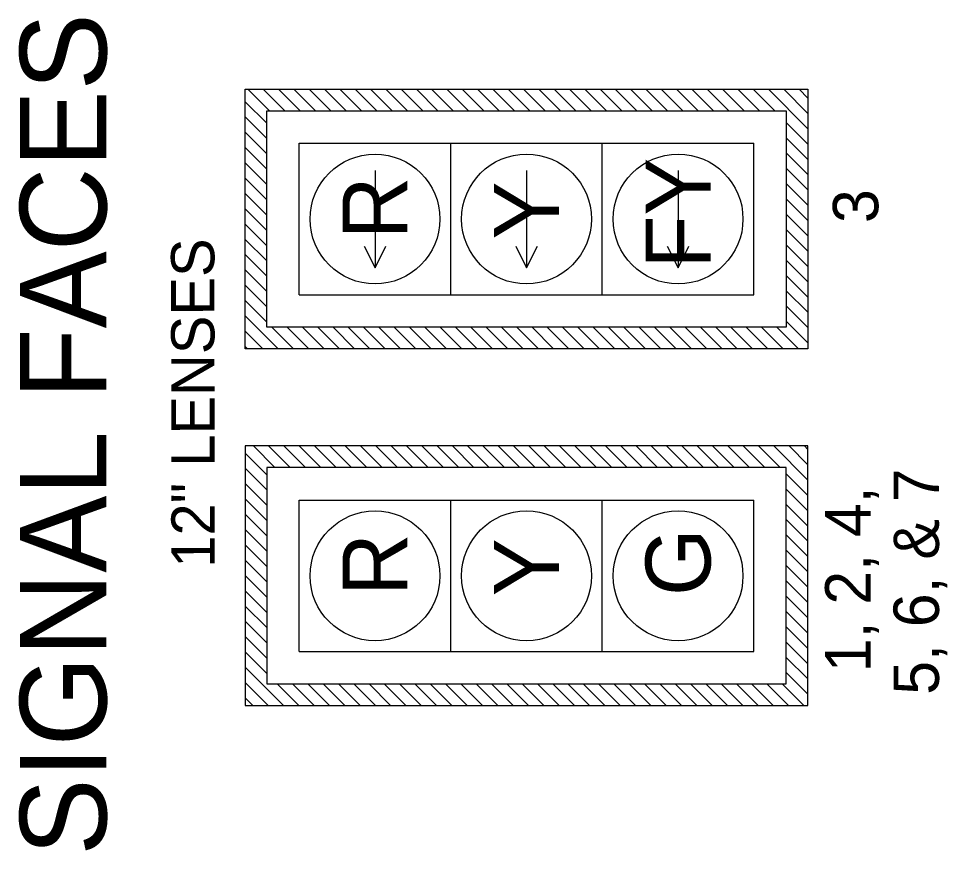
# Model space of a CAD drawing. Extents: x 610543 to 611161, y 419122 to 420064.
# Drawn here: x 610545.3 to 610631.1, y 419293.9 to 419370.8 of the extents above; entities that cross this region are included whole.
import ezdxf

# ---------------------------------------------------------------- set-up
doc = ezdxf.new("R2010")
doc.units = 0
for name, color, linetype in [('C-ANNO-TEXT', 7, 'Continuous'), ('Level 61', 7, 'Continuous'), ('T_Drafting', 7, 'Continuous')]:
    doc.layers.add(name, color=color, linetype=linetype)

msp = doc.modelspace()

# ---------------------------------------------------------------- linework, layer by layer
at = {"layer": 'T_Drafting'}
for p, q in [((610566.202, 419340.257), (610566.202, 419364.257)), ((610566.202, 419364.257), (610618.202, 419364.257)), ((610568.465, 419362.257), (610566.465, 419364.257)), ((610569.879, 419362.257), (610567.879, 419364.257)), ((610571.293, 419362.257), (610569.293, 419364.257)), ((610572.708, 419362.257), (610570.708, 419364.257)), ((610574.122, 419362.257), (610572.122, 419364.257)), ((610575.536, 419362.257), (610573.536, 419364.257)), ((610576.95, 419362.257), (610574.95, 419364.257)), ((610578.364, 419362.257), (610576.364, 419364.257)), ((610579.779, 419362.257), (610577.779, 419364.257)), ((610581.193, 419362.257), (610579.193, 419364.257)), ((610582.607, 419362.257), (610580.607, 419364.257)), ((610584.021, 419362.257), (610582.021, 419364.257)), ((610585.436, 419362.257), (610583.436, 419364.257)), ((610586.85, 419362.257), (610584.85, 419364.257)), ((610588.264, 419362.257), (610586.264, 419364.257)), ((610589.678, 419362.257), (610587.678, 419364.257)), ((610591.092, 419362.257), (610589.092, 419364.257)), ((610592.507, 419362.257), (610590.507, 419364.257)), ((610593.921, 419362.257), (610591.921, 419364.257)), ((610595.335, 419362.257), (610593.335, 419364.257)), ((610596.749, 419362.257), (610594.749, 419364.257)), ((610598.163, 419362.257), (610596.163, 419364.257)), ((610599.578, 419362.257), (610597.578, 419364.257)), ((610600.992, 419362.257), (610598.992, 419364.257)), ((610602.406, 419362.257), (610600.406, 419364.257)), ((610603.82, 419362.257), (610601.82, 419364.257)), ((610605.235, 419362.257), (610603.235, 419364.257)), ((610606.649, 419362.257), (610604.649, 419364.257)), ((610608.063, 419362.257), (610606.063, 419364.257)), ((610609.477, 419362.257), (610607.477, 419364.257)), ((610610.891, 419362.257), (610608.891, 419364.257)), ((610612.306, 419362.257), (610610.306, 419364.257)), ((610613.72, 419362.257), (610611.72, 419364.257)), ((610615.134, 419362.257), (610613.134, 419364.257)), ((610618.202, 419360.603), (610614.548, 419364.257)), ((610618.202, 419362.018), (610615.962, 419364.257)), ((610618.202, 419363.432), (610617.377, 419364.257)), ((610618.202, 419364.257), (610618.202, 419340.257)), ((610568.202, 419361.106), (610566.202, 419363.106)), ((610568.202, 419359.692), (610566.202, 419361.692)), ((610618.202, 419359.189), (610616.202, 419361.189)), ((610568.202, 419358.277), (610566.202, 419360.277)), ((610618.202, 419357.775), (610616.202, 419359.775)), ((610568.202, 419356.863), (610566.202, 419358.863)), ((610571.202, 419345.257), (610571.202, 419359.257)), ((610571.202, 419359.257), (610585.202, 419359.257)), ((610585.202, 419345.257), (610585.202, 419359.257)), ((610585.202, 419359.257), (610599.202, 419359.257)), ((610599.202, 419345.257), (610599.202, 419359.257)), ((610599.202, 419359.257), (610613.202, 419359.257)), ((610613.202, 419345.257), (610613.202, 419359.257)), ((610618.202, 419356.361), (610616.202, 419358.361)), ((610568.202, 419355.449), (610566.202, 419357.449)), ((610578.202, 419356.757), (610578.202, 419347.757)), ((610592.202, 419356.757), (610592.202, 419347.757)), ((610606.202, 419356.757), (610606.202, 419347.757)), ((610618.202, 419354.946), (610616.202, 419356.946)), ((610568.202, 419354.035), (610566.202, 419356.035)), ((610618.202, 419353.532), (610616.202, 419355.532)), ((610568.202, 419352.621), (610566.202, 419354.621)), ((610618.202, 419352.118), (610616.202, 419354.118)), ((610568.202, 419351.206), (610566.202, 419353.206)), ((610618.202, 419350.704), (610616.202, 419352.704)), ((610568.202, 419349.792), (610566.202, 419351.792)), ((610618.202, 419349.29), (610616.202, 419351.29)), ((610568.202, 419348.378), (610566.202, 419350.378)), ((610618.202, 419347.875), (610616.202, 419349.875)), ((610568.202, 419346.964), (610566.202, 419348.964)), ((610618.202, 419346.461), (610616.202, 419348.461)), ((610568.202, 419345.549), (610566.202, 419347.549)), ((610618.202, 419345.047), (610616.202, 419347.047)), ((610568.202, 419344.135), (610566.202, 419346.135)), ((610618.202, 419343.633), (610616.202, 419345.633)), ((610568.202, 419342.721), (610566.202, 419344.721)), ((610571.202, 419345.257), (610585.202, 419345.257)), ((610585.202, 419345.257), (610599.202, 419345.257)), ((610599.202, 419345.257), (610613.202, 419345.257)), ((610618.202, 419342.219), (610616.202, 419344.219)), ((610569.252, 419340.257), (610566.202, 419343.307)), ((610570.666, 419340.257), (610568.666, 419342.257)), ((610572.08, 419340.257), (610570.08, 419342.257)), ((610573.494, 419340.257), (610571.494, 419342.257)), ((610574.909, 419340.257), (610572.909, 419342.257)), ((610576.323, 419340.257), (610574.323, 419342.257)), ((610577.737, 419340.257), (610575.737, 419342.257)), ((610579.151, 419340.257), (610577.151, 419342.257)), ((610580.565, 419340.257), (610578.565, 419342.257)), ((610581.98, 419340.257), (610579.98, 419342.257)), ((610583.394, 419340.257), (610581.394, 419342.257)), ((610584.808, 419340.257), (610582.808, 419342.257)), ((610586.222, 419340.257), (610584.222, 419342.257)), ((610587.637, 419340.257), (610585.637, 419342.257)), ((610589.051, 419340.257), (610587.051, 419342.257)), ((610590.465, 419340.257), (610588.465, 419342.257)), ((610591.879, 419340.257), (610589.879, 419342.257)), ((610593.293, 419340.257), (610591.293, 419342.257)), ((610594.708, 419340.257), (610592.708, 419342.257)), ((610596.122, 419340.257), (610594.122, 419342.257)), ((610597.536, 419340.257), (610595.536, 419342.257)), ((610598.95, 419340.257), (610596.95, 419342.257)), ((610600.364, 419340.257), (610598.364, 419342.257)), ((610601.779, 419340.257), (610599.779, 419342.257)), ((610603.193, 419340.257), (610601.193, 419342.257)), ((610604.607, 419340.257), (610602.607, 419342.257)), ((610606.021, 419340.257), (610604.021, 419342.257)), ((610607.436, 419340.257), (610605.436, 419342.257)), ((610608.85, 419340.257), (610606.85, 419342.257)), ((610610.264, 419340.257), (610608.264, 419342.257)), ((610611.678, 419340.257), (610609.678, 419342.257)), ((610613.092, 419340.257), (610611.092, 419342.257)), ((610614.507, 419340.257), (610612.507, 419342.257)), ((610615.921, 419340.257), (610613.921, 419342.257)), ((610617.335, 419340.257), (610615.335, 419342.257)), ((610618.202, 419340.804), (610616.202, 419342.804)), ((610567.838, 419340.257), (610566.202, 419341.893)), ((610566.423, 419340.257), (610566.202, 419340.478)), ((610618.202, 419340.257), (610566.202, 419340.257)), ((610618.202, 419331.278), (610566.202, 419331.278)), ((610566.202, 419331.278), (610566.202, 419307.278)), ((610568.962, 419329.278), (610566.962, 419331.278)), ((610570.376, 419329.278), (610568.376, 419331.278)), ((610571.79, 419329.278), (610569.79, 419331.278)), ((610573.204, 419329.278), (610571.204, 419331.278)), ((610574.619, 419329.278), (610572.619, 419331.278)), ((610576.033, 419329.278), (610574.033, 419331.278)), ((610577.447, 419329.278), (610575.447, 419331.278)), ((610578.861, 419329.278), (610576.861, 419331.278)), ((610580.276, 419329.278), (610578.276, 419331.278)), ((610581.69, 419329.278), (610579.69, 419331.278)), ((610583.104, 419329.278), (610581.104, 419331.278)), ((610584.518, 419329.278), (610582.518, 419331.278)), ((610585.932, 419329.278), (610583.932, 419331.278)), ((610587.347, 419329.278), (610585.347, 419331.278)), ((610588.761, 419329.278), (610586.761, 419331.278)), ((610590.175, 419329.278), (610588.175, 419331.278)), ((610591.589, 419329.278), (610589.589, 419331.278)), ((610593.003, 419329.278), (610591.003, 419331.278)), ((610594.418, 419329.278), (610592.418, 419331.278)), ((610595.832, 419329.278), (610593.832, 419331.278)), ((610597.246, 419329.278), (610595.246, 419331.278)), ((610598.66, 419329.278), (610596.66, 419331.278)), ((610600.075, 419329.278), (610598.075, 419331.278)), ((610601.489, 419329.278), (610599.489, 419331.278)), ((610602.903, 419329.278), (610600.903, 419331.278)), ((610604.317, 419329.278), (610602.317, 419331.278)), ((610605.731, 419329.278), (610603.731, 419331.278)), ((610607.146, 419329.278), (610605.146, 419331.278)), ((610608.56, 419329.278), (610606.56, 419331.278)), ((610609.974, 419329.278), (610607.974, 419331.278)), ((610611.388, 419329.278), (610609.388, 419331.278)), ((610612.802, 419329.278), (610610.802, 419331.278)), ((610614.217, 419329.278), (610612.217, 419331.278)), ((610615.631, 419329.278), (610613.631, 419331.278)), ((610618.202, 419328.121), (610615.045, 419331.278)), ((610618.202, 419329.536), (610616.459, 419331.278)), ((610618.202, 419330.95), (610617.874, 419331.278)), ((610618.202, 419307.278), (610618.202, 419331.278)), ((610568.202, 419328.624), (610566.202, 419330.624)), ((610568.202, 419327.21), (610566.202, 419329.21)), ((610618.202, 419326.707), (610616.202, 419328.707)), ((610568.202, 419325.796), (610566.202, 419327.796)), ((610618.202, 419325.293), (610616.202, 419327.293)), ((610568.202, 419324.381), (610566.202, 419326.381)), ((610571.202, 419312.278), (610571.202, 419326.278)), ((610571.202, 419326.278), (610585.202, 419326.278)), ((610585.202, 419312.278), (610585.202, 419326.278)), ((610585.202, 419326.278), (610599.202, 419326.278)), ((610599.202, 419312.278), (610599.202, 419326.278)), ((610599.202, 419326.278), (610613.202, 419326.278)), ((610613.202, 419312.278), (610613.202, 419326.278)), ((610618.202, 419323.879), (610616.202, 419325.879)), ((610568.202, 419322.967), (610566.202, 419324.967)), ((610618.202, 419322.465), (610616.202, 419324.465)), ((610568.202, 419321.553), (610566.202, 419323.553)), ((610618.202, 419321.05), (610616.202, 419323.05)), ((610568.202, 419320.139), (610566.202, 419322.139)), ((610618.202, 419319.636), (610616.202, 419321.636)), ((610568.202, 419318.724), (610566.202, 419320.724)), ((610618.202, 419318.222), (610616.202, 419320.222)), ((610568.202, 419317.31), (610566.202, 419319.31)), ((610618.202, 419316.808), (610616.202, 419318.808)), ((610568.202, 419315.896), (610566.202, 419317.896)), ((610618.202, 419315.394), (610616.202, 419317.394)), ((610568.202, 419314.482), (610566.202, 419316.482)), ((610618.202, 419313.979), (610616.202, 419315.979)), ((610568.202, 419313.068), (610566.202, 419315.068)), ((610618.202, 419312.565), (610616.202, 419314.565)), ((610568.202, 419311.653), (610566.202, 419313.653)), ((610618.202, 419311.151), (610616.202, 419313.151)), ((610568.202, 419310.239), (610566.202, 419312.239)), ((610571.202, 419312.278), (610585.202, 419312.278)), ((610585.202, 419312.278), (610599.202, 419312.278)), ((610599.202, 419312.278), (610613.202, 419312.278)), ((610618.202, 419309.737), (610616.202, 419311.737)), ((610569.749, 419307.278), (610566.202, 419310.825)), ((610618.202, 419308.322), (610616.202, 419310.322)), ((610568.334, 419307.278), (610566.202, 419309.411)), ((610571.163, 419307.278), (610569.163, 419309.278)), ((610572.577, 419307.278), (610570.577, 419309.278)), ((610573.991, 419307.278), (610571.991, 419309.278)), ((610575.405, 419307.278), (610573.405, 419309.278)), ((610576.82, 419307.278), (610574.82, 419309.278)), ((610578.234, 419307.278), (610576.234, 419309.278)), ((610579.648, 419307.278), (610577.648, 419309.278)), ((610581.062, 419307.278), (610579.062, 419309.278)), ((610582.477, 419307.278), (610580.477, 419309.278)), ((610583.891, 419307.278), (610581.891, 419309.278)), ((610585.305, 419307.278), (610583.305, 419309.278)), ((610586.719, 419307.278), (610584.719, 419309.278)), ((610588.133, 419307.278), (610586.133, 419309.278)), ((610589.548, 419307.278), (610587.548, 419309.278)), ((610590.962, 419307.278), (610588.962, 419309.278)), ((610592.376, 419307.278), (610590.376, 419309.278)), ((610593.79, 419307.278), (610591.79, 419309.278)), ((610595.204, 419307.278), (610593.204, 419309.278)), ((610596.619, 419307.278), (610594.619, 419309.278)), ((610598.033, 419307.278), (610596.033, 419309.278)), ((610599.447, 419307.278), (610597.447, 419309.278)), ((610600.861, 419307.278), (610598.861, 419309.278)), ((610602.276, 419307.278), (610600.276, 419309.278)), ((610603.69, 419307.278), (610601.69, 419309.278)), ((610605.104, 419307.278), (610603.104, 419309.278)), ((610606.518, 419307.278), (610604.518, 419309.278)), ((610607.932, 419307.278), (610605.932, 419309.278)), ((610609.347, 419307.278), (610607.347, 419309.278)), ((610610.761, 419307.278), (610608.761, 419309.278)), ((610612.175, 419307.278), (610610.175, 419309.278)), ((610613.589, 419307.278), (610611.589, 419309.278)), ((610615.003, 419307.278), (610613.003, 419309.278)), ((610616.418, 419307.278), (610614.418, 419309.278)), ((610617.832, 419307.278), (610615.832, 419309.278)), ((610566.92, 419307.278), (610566.202, 419307.997)), ((610566.202, 419307.278), (610618.202, 419307.278))]:
    msp.add_line(p, q, dxfattribs=at)
for points in [[(610568.202, 419342.257), (610568.202, 419362.257), (610616.202, 419362.257), (610616.202, 419342.257)], [(610616.202, 419329.278), (610568.202, 419329.278), (610568.202, 419309.278), (610616.202, 419309.278)]]:
    msp.add_lwpolyline(points, close=True, dxfattribs=at)
for points in [[(610577.202, 419349.757), (610578.202, 419347.757), (610579.202, 419349.757)], [(610591.202, 419349.757), (610592.202, 419347.757), (610593.202, 419349.757)], [(610605.202, 419349.757), (610606.202, 419347.757), (610607.202, 419349.757)]]:
    msp.add_lwpolyline(points, dxfattribs=at)
for centre in [(610578.202, 419352.257), (610592.202, 419352.257), (610606.202, 419352.257), (610578.202, 419319.278), (610592.202, 419319.278), (610606.202, 419319.278)]:
    msp.add_circle(centre, 6, dxfattribs=at)

# ---------------------------------------------------------------- texts
at = {"layer": 'C-ANNO-TEXT'}
for s, p in [('3', (610624.704, 419351.885)), ('5, 6, & 7', (610630.308, 419308.279)), ('1, 2, 4, ', (610623.988, 419310.364))]:
    msp.add_text(s, height=4.2, rotation=90, dxfattribs=at).set_placement(p)
at = {"layer": 'Level 61'}
for s, height, rotation, p in [('SIGNAL FACES', 8, 90, (610553.39, 419293.401)), ('12" LENSES', 4, 90.07203, (610563.395, 419320.025))]:
    msp.add_text(s, height=height, rotation=rotation, dxfattribs=at).set_placement(p)
at = {"layer": 'T_Drafting'}
for s, height, p in [('FY', 5.9978, (610609.201, 419347.674)), ('R', 5.998, (610581.201, 419350.392)), ('Y', 5.998, (610595.201, 419350.368)), ('R', 5.998, (610581.201, 419317.413)), ('Y', 5.998, (610595.201, 419317.389)), ('G', 5.998, (610609.201, 419317.412))]:
    msp.add_text(s, height=height, rotation=90, dxfattribs=at).set_placement(p)

doc.saveas('drawing.dxf')
